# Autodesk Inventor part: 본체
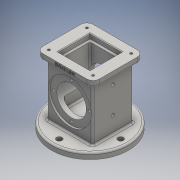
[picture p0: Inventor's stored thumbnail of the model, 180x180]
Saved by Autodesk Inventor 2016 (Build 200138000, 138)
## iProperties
Created: 2018-10
Part Number: 본체
Material: 일반
Document SubType Name: Modeling
Designer: 3sil_cad019
Density: 1 g/cm^3
Appearance: 기본값
Author: 3sil_cad019
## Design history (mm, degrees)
sketch "스케치1"
  geometry: L1 (-37, 33)-(37, 33); L2 (37, 33)-(37, -33); L3 (37, -33)-(-37, -33); L4 (-37, -33)-(-37, 33); 3 further points
  constraints: 8 end point, 2 midpoint, 2 parallel, 1 horizontal, 1 horizontal alignment, 1 perpendicular, 1 vertical alignment
  dimensions: "d0" = 74 distance of L1.start L1.end; "d1" = 66 distance of L3.end L1.start
extrude "돌출1" new body sketch "스케치1" distance "d2" = 108; taper "d3" = 0 deg
sketch "스케치2"
  geometry: L1 (74, 0)-(0, 0) reference; C1 r 24 at (37, 54); 2 further points
  constraints: 1 centre point, 1 midpoint, 1 vertical alignment
  dimensions: "d4" = 48 diameter of C1; "d5" = 54 distance from line of C1.centre L1
extrude "돌출2" cut sketch "스케치2" stored distance "d6" = 108; taper "d7" = 0 deg
sketch "스케치3"
  geometry: C1 r 24 at (37, 54) reference; C2 r 35 at (37, 54); 1 further point
  constraints: 1 centre point, 1 coincident
  dimensions: "d8" = 70 diameter of C2
extrude "돌출3" cut sketch "스케치3" distance "d9" = 3; taper "d10" = 0 deg
sketch "스케치4"
  geometry: C1 r 62.5 at (0, 0); 1 further point
  constraints: 1 centre point, 1 coincident
  dimensions: "d11" = 125 diameter of C1
extrude "돌출4" join sketch "스케치4" distance "d12" = 10; taper "d13" = 0 deg
sketch "스케치5"
  geometry: L1 (-46, 41)-(46, 41); L2 (46, 41)-(46, -41); L3 (46, -41)-(-46, -41); L4 (-46, -41)-(-46, 41); 3 further points
  constraints: 8 end point, 2 midpoint, 2 parallel, 1 horizontal, 1 horizontal alignment, 1 perpendicular, 1 vertical alignment
  dimensions: "d14" = 92 distance of L1.start L1.end; "d15" = 82 distance of L1.end L2.end
extrude "돌출5" join sketch "스케치5" distance "d16" = 10; taper "d17" = 0 deg
sketch "스케치6"
  geometry: L1 (-22, 22)-(22, 22); L2 (22, 22)-(22, -22); L3 (22, -22)-(-22, -22); L4 (-22, -22)-(-22, 22); 3 further points
  constraints: 8 end point, 2 midpoint, 2 parallel, 1 horizontal, 1 horizontal alignment, 1 perpendicular, 1 vertical alignment
  dimensions: "d18" = 44 distance of L1.start L1.end; "d19" = 44 distance of L3.end L1.start
extrude "돌출6" cut sketch "스케치6" distance "d20" = 82; taper "d21" = 0 deg
sketch "스케치7"
  geometry: L1 (-26, 26)-(26, 26); L2 (26, 26)-(26, -26); L3 (26, -26)-(-26, -26); L4 (-26, -26)-(-26, 26); 3 further points
  constraints: 8 end point, 2 midpoint, 2 parallel, 1 horizontal, 1 horizontal alignment, 1 perpendicular, 1 vertical alignment
  dimensions: "d22" = 52 distance of L1.start L1.end; "d24" = 52 distance of L1.end L2.end
extrude "돌출7" cut sketch "스케치7" distance "d25" = 8; taper "d26" = 0 deg
sketch "스케치8"
  geometry: C1 r 28 at (0, 0); 1 further point
  constraints: 1 centre point, 1 coincident
  dimensions: "d27" = 56 diameter of C1
extrude "돌출8" cut sketch "스케치8" distance "d28" = 18; taper "d29" = -10 deg
sketch "스케치9"
  geometry: C1 r 24 at (0, 0) reference; 2 further points
  constraints: 1 vertical alignment
  dimensions: "d30" = 29 distance of C1.centre point (0, 29)
hole "구멍1" sketch "스케치9" at (0, 29) diameter "d31" = 4; stored, may be unused: countersink angle "d35" = 90 deg, drill point angle "d37" = 118 deg; dims "d32" = 6, "d33" = 4, "d34" = 2, "d36" = 6
fillet "모깎기1" dims "d44" = 10
sketch "스케치11"
  geometry: L1 (-46, -31)-(-46, 31) reference; L2 (36, -41)-(-36, -41) reference; L3 (46, 31)-(46, -31) reference; L4 (-36, 41)-(36, 41) reference; L5 (-26, -26)-(-26, 26) reference; L6 (-26, 26)-(26, 26) reference; L7 (26, 26)-(26, -26) reference; L8 (26, -26)-(-26, -26) reference; A1 r 10 centre (-36, 31) between (-36, 41) and (-46, 31) reference; A2 r 10 centre (-36, -31) between (-46, -31) and (-36, -41) reference; A3 r 10 centre (36, -31) between (36, -41) and (46, -31) reference; A4 r 10 centre (36, 31) between (46, 31) and (36, 41) reference; 1 further point
hole "구멍2" sketch "스케치11" at (-36, -31), (-36, 31), (36, 31), (36, -31) diameter "d45" = 4; stored, may be unused: countersink angle "d49" = 90 deg, drill point angle "d51" = 118 deg; dims "d46" = 6, "d47" = 4, "d48" = 2, "d50" = 6
sketch "스케치12" dims "d52" = 100
  geometry: C1 r 62.5 at (0, 0) reference; 3 further points
  constraints: 2 vertical alignment, 1 coincident, 2 other
hole "구멍3" sketch "스케치12" at (0, 50) diameter "d53" = 9; stored, may be unused: countersink angle "d57" = 90 deg, drill point angle "d59" = 118 deg; dims "d54" = 6, "d55" = 4, "d56" = 2, "d58" = 6
sketch "스케치13"
  geometry: L1 (-10, 0)-(-10, -10) reference; L2 (72, 0)-(0, 0) reference; 2 further points
  constraints: 1 other
  dimensions: "d63" = 46 distance from line of point (36, -4) L1; "d64" = 4 distance from line of point (36, -4) L2
feature "엠보싱1" sketch "스케치13" dims "d0" = 74, "d1" = 66, "d65" = 0.5, "d66" = 0
sketch "스케치15"
  geometry: L1 (-98, 64)-(-98, 2) reference; L2 (10, 95.5)-(10, -29.5) reference; 4 further points
  constraints: 2 horizontal alignment, 1 midpoint
  dimensions: "d69" = 37 distance from line of point (-27, 33) L2; "d70" = 43 distance of point (-27, 33) point (-70, 33)
hole "구멍4" sketch "스케치15" at (-70, 33), (-27, 33) diameter "d71" = 5; stored, may be unused: countersink angle "d75" = 90 deg, drill point angle "d77" = 118 deg; dims "d72" = 6, "d73" = 4, "d74" = 2, "d76" = 17.75
fillet "모깎기2" dims "d78" = 3
fillet "모깎기3" dims "d79" = 3
fillet "모깎기4" dims "d80" = 3
fillet "모깎기5" dims "d81" = 3
chamfer "모따기1" distance "d82" = 1; stored, may be unused: second distance "d83" = 2, angle "d84" = 45 deg
node "솔리드1"
mirror "대칭1"
pattern_circular "원형 패턴1" dims angle "d39" = 360 deg
mirror "대칭2"
pattern_circular "원형 패턴2" dims angle "d61" = 360 deg
node "투영된 루프1"
